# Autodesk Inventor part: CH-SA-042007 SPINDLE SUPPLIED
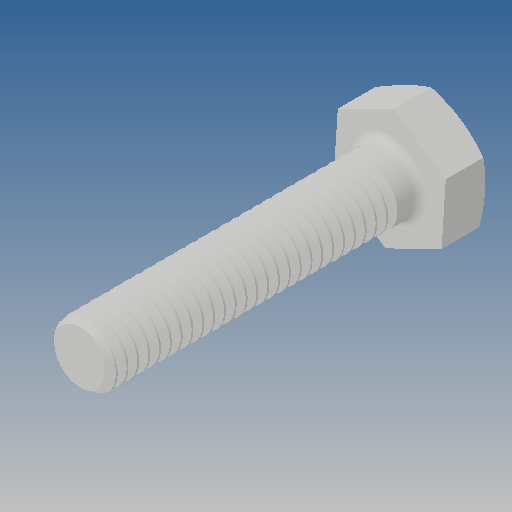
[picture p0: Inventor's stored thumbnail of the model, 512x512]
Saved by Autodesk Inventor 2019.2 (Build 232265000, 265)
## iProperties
Created: 2012-09
Part Number: CH-SA-042007 SPINDLE SUPPLIED
Material: Ogólny
Document SubType Name: Modeling
Designer: CADENGINEERING4
Density: 1 g/cm^3
Appearance: Domyślna
Author: CADENGINEERING4
Revision Number: ÈÎºÎ
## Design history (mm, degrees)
feature "ÇÐ³ý-É¨Ãè1"
node "Bryła1"
